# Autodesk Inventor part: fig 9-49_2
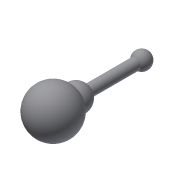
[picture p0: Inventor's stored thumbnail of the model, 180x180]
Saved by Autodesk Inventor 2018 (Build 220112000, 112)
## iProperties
Created: 2013-03
Part Number: fig 9-49_2
Material: Generic
Document SubType Name: Modeling
Designer: CADCIM
Density: 1 g/cm^3
Appearance: Default
Author: CADCIM
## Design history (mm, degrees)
sketch "Sketch1"
  geometry: L1 (0, 5)-(0, -5); A1 r 5 centre (0, 0) between (0, -5) and (0, 5); 1 further point
  constraints: 2 end point, 2 point on circle, 1 centre point, 1 coincident, 1 vertical
  dimensions: "d0" = 10 diameter of A1
revolve "Revolution1" sketch "Sketch1" stored, may be unused: angle "d2" = 90 deg
sketch "Sketch2"
  geometry: L1 (0, 20.921)-(0, 2.139); L2 (1.175, 7.426)-(1.175, 17.742); A1 r 1.807 centre (0, 19.115) between (1.175, 17.742) and (0, 20.921); A2 r 2.774 centre (0, 4.913) between (0, 2.139) and (1.175, 7.426); 1 further point
  constraints: 4 end point, 4 point on circle, 2 centre point, 1 parallel, 1 vertical
revolve "Revolution2" sketch "Sketch2" stored, may be unused: angle "d3" = 90 deg
body "Solid1"
